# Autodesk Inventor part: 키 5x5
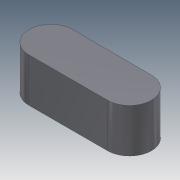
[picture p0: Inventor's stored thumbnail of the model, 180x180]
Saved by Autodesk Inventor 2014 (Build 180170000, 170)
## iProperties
Company: 한국ATC센터
Created: 2014-10
Part Number: 키 5x5
Document SubType Name: Modeling
Designer: KYOUNG IL JANG
Density: 1 g/cm^3
Mass: 0.323175 g
Surface Area: 2.9781 cm^2
Volume: 0.323175 cm^3
Material: Generic
Appearance: Steel - Polished
Author: KYOUNG IL JANG
Revision Number: 1
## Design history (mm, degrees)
sketch "스케치1"
  geometry: L1 (-4.5, -2.5)-(4.5, -2.5); L2 (4.5, 2.5)-(-4.5, 2.5); A1 r 2.5 centre (4.5, 0) between (4.5, -2.5) and (4.5, 2.5); A2 r 2.5 centre (-4.5, 0) between (-4.5, 2.5) and (-4.5, -2.5); 2 further points
  constraints: 4 end point, 4 point on circle, 4 tangent, 2 centre point, 1 horizontal, 1 horizontal alignment, 1 midpoint, 1 parallel, 1 vertical alignment
  dimensions: "d0" = 5 distance between parallel lines of L1 L2; "d1" = 14 dimension on A1 A2
extrude "돌출1" new body sketch "스케치1" stored distance "d2" = 5; taper "d3" = 0 deg
node "솔리드1"
